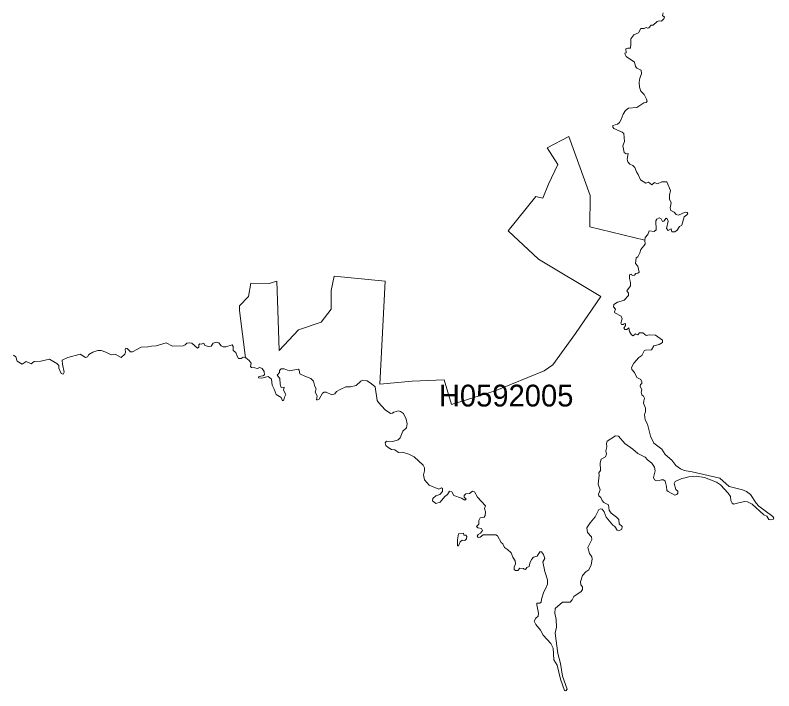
# Model space of a CAD drawing. Extents: x 369010 to 739155, y 6377141 to 6616555.
# Drawn here: x 428344 to 431823, y 6458107 to 6461206 of the extents above; entities that cross this region are included whole.
import ezdxf
from ezdxf.enums import TextEntityAlignment as Align

# ---------------------------------------------------------------- set-up
doc = ezdxf.new("R2010")
doc.units = 0
doc.header["$LTSCALE"] = 40
doc.layers.add('1', color=7, linetype='Continuous', lineweight=13)
doc.layers.add('2', color=7, linetype='Continuous')

msp = doc.modelspace()

# ---------------------------------------------------------------- linework, layer by layer
at = {"layer": '1'}
for points in [[(431238.22, 6460805.91), (431242.03, 6460812.03), (431240.04, 6460821.46), (431228.29, 6460842.48), (431213.73, 6460858.04), (431207.27, 6460875.91), (431206.28, 6460899.09), (431208.1, 6460918.28), (431216.54, 6460937.15), (431215.21, 6460953.54), (431195.52, 6460963.96), (431189.4, 6460971.41), (431185.09, 6460990.77), (431145.54, 6461017.09), (431140.9, 6461026.03), (431140.41, 6461032.15), (431146.03, 6461034.47), (431145.04, 6461051.35), (431153.98, 6461055.16), (431165.73, 6461055.16), (431168.21, 6461075.35), (431167.22, 6461097.52), (431180.79, 6461116.39), (431202.47, 6461124.83), (431213.23, 6461145.02), (431227.96, 6461145.52), (431237.72, 6461149.66), (431244.18, 6461146.85), (431249.97, 6461147.84), (431260.07, 6461160.58), (431270.49, 6461160.09), (431287.87, 6461177.96), (431297.3, 6461179.78), (431307.57, 6461178.95), (431318.49, 6461189.71), (431321.3, 6461197.65), (431312.37, 6461204.27), (431315.18, 6461216.52)], [(429544.62, 6459986.17), (429548.92, 6459852.77), (429554.71, 6459668.23), (429644.09, 6459763.4), (429747.86, 6459797.99), (429794.03, 6459858.56), (429793.7, 6459943.13), (429806.94, 6460009.17), (430041.3, 6459986.17), (430016.14, 6459514.64), (430165.42, 6459528.38), (430311.23, 6459533.02), (430345.66, 6459420.8), (430545.75, 6459483.86), (430769.84, 6459574.56), (430809.23, 6459602.2), (430914.16, 6459746.68), (431030.51, 6459915.83), (430743.69, 6460087.95), (430604.34, 6460217.04), (430732.11, 6460375.43), (430763.39, 6460367.82), (430789.54, 6460430.87), (430832.24, 6460521.57), (430784.57, 6460598.36), (430882.88, 6460649.84), (430981.52, 6460378.74), (430979.54, 6460236.08), (431231.27, 6460174.84), (431231.1, 6460175.01), (431233.59, 6460186.92), (431246.16, 6460200), (431251.46, 6460216.88), (431275.29, 6460214.56), (431284.23, 6460221.68), (431282.91, 6460263.05), (431287.54, 6460271.49), (431297.97, 6460276.13), (431305.91, 6460272.98), (431313.03, 6460260.74), (431319.15, 6460262.06), (431329.41, 6460275.8), (431334.21, 6460272.98), (431338.35, 6460262.06), (431331.4, 6460227.8), (431339.34, 6460218.86), (431352.09, 6460225.82), (431356.22, 6460212.74), (431369.96, 6460212.74), (431380.72, 6460220.19), (431391.48, 6460237.24), (431400.91, 6460243.36), (431411.83, 6460281.92), (431424.91, 6460289.87), (431429.21, 6460297.31), (431425.9, 6460301.62), (431415.97, 6460302.61), (431386.84, 6460289.37), (431376.08, 6460291.69), (431365.66, 6460302.11), (431350.6, 6460310.55), (431348.28, 6460322.8), (431352.58, 6460345.31), (431345.47, 6460361.86), (431345.47, 6460381.06), (431349.77, 6460402.24), (431332.23, 6460442.29), (431310.21, 6460442.29), (431289.53, 6460433.36), (431276.29, 6460438.49), (431264.04, 6460428.23), (431248.98, 6460439.98), (431236.4, 6460436.17), (431211.41, 6460450.74), (431201.15, 6460476.06), (431193.04, 6460487.81), (431186.42, 6460507.67), (431176.16, 6460517.1), (431162.92, 6460523.23), (431154.47, 6460534.48), (431150.67, 6460546.23), (431155.96, 6460571.22), (431146.03, 6460570.73), (431137.59, 6460576.35), (431130.97, 6460606.97), (431138.92, 6460626.67), (431135.77, 6460663.74), (431127.66, 6460670.36), (431090.09, 6460685.92), (431084.47, 6460692.54), (431085.29, 6460699.98), (431106.98, 6460706.6), (431115.91, 6460714.22), (431123.03, 6460727.29), (431132.96, 6460753.11), (431142.72, 6460768.67), (431156.46, 6460779.59), (431195.02, 6460783.73), (431226.47, 6460803.92), (431238.22, 6460805.91)], [(431184.1, 6460013.31), (431189.73, 6460021.75), (431199.16, 6460023.07), (431205.28, 6460027.38), (431200.15, 6460055.18), (431188.9, 6460067.76), (431191.71, 6460093.25), (431200.15, 6460097.38), (431208.1, 6460116.75), (431213.23, 6460132.31), (431233.59, 6460155.81), (431231.27, 6460174.84), (430979.54, 6460236.08), (430981.52, 6460378.74), (430882.88, 6460649.84), (430784.57, 6460598.36), (430832.24, 6460521.57), (430789.54, 6460430.87), (430763.39, 6460367.82), (430732.11, 6460375.43), (430604.34, 6460217.04), (430743.69, 6460087.95), (431030.51, 6459915.83), (430914.16, 6459746.68), (430809.23, 6459602.2), (430769.84, 6459574.56), (430545.75, 6459483.86), (430345.66, 6459420.8), (430311.23, 6459533.02), (430165.42, 6459528.38), (430016.14, 6459514.64), (430041.3, 6459986.17), (429806.94, 6460009.17), (429793.7, 6459943.13), (429794.03, 6459858.56), (429747.86, 6459797.99), (429644.09, 6459763.4), (429554.71, 6459668.23), (429548.92, 6459852.77), (429544.62, 6459986.17), (429508.87, 6459975.41), (429425.29, 6459977.06), (429413.87, 6459915.5), (429372.82, 6459873.95), (429372.82, 6459852.44), (429401.13, 6459635.3)], [(431631.95, 6458967.65), (431640.39, 6458962.85), (431655.46, 6458968.48), (431689.71, 6458976.09), (431702.96, 6458974.11), (431724.14, 6458963.35), (431778.09, 6458914.03), (431790.84, 6458907.91), (431800.77, 6458893.18), (431809.71, 6458891.36), (431820.96, 6458893.18), (431823.28, 6458898.97), (431819.14, 6458907.41), (431754.26, 6458954.91), (431742.01, 6458967.98), (431716.53, 6459007.04), (431698.65, 6459021.28), (431680.28, 6459028.72), (431617.72, 6459044.28), (431576.34, 6459082.84), (431448.41, 6459112.47), (431412.66, 6459117.6), (431394.79, 6459126.04), (431374.6, 6459140.27), (431355.73, 6459165.1), (431324.28, 6459191.91), (431309.22, 6459215.91), (431272.48, 6459243.71), (431257.91, 6459274.83), (431243.35, 6459330.27), (431233.59, 6459349.97), (431230.77, 6459374.96), (431235.41, 6459386.71), (431235.41, 6459403.59), (431224.98, 6459426.76), (431226.97, 6459437.52), (431230.77, 6459449.77), (431225.97, 6459458.21), (431218.53, 6459465.32), (431215.21, 6459477.08), (431217.53, 6459488.33), (431210.08, 6459504.22), (431212.4, 6459512.33), (431218.53, 6459516.47), (431218.03, 6459525.07), (431212.9, 6459535.83), (431195.35, 6459543.77), (431184.1, 6459566.78), (431172.85, 6459581.01), (431171.03, 6459590.78), (431181.78, 6459610.64), (431203.96, 6459636.95), (431217.53, 6459644.9), (431228.29, 6459666.58), (431234.91, 6459670.38), (431261.72, 6459670.88), (431272.98, 6459689.58), (431296.97, 6459695.71), (431312.03, 6459705.14), (431312.03, 6459715.07), (431280.09, 6459739.07), (431253.78, 6459739.56), (431237.72, 6459736.75), (431222.66, 6459748.83), (431207.6, 6459749.33), (431200.15, 6459739.9), (431188.9, 6459744.2), (431178.97, 6459736.25), (431170.03, 6459740.39), (431161.59, 6459755.45), (431158.78, 6459772), (431149.84, 6459763.89), (431140.41, 6459764.39), (431136.1, 6459771.01), (431142.72, 6459783.26), (431142.72, 6459791.7), (431137.1, 6459790.71), (431132.46, 6459787.06), (431124.35, 6459787.4), (431121.54, 6459793.19), (431127.66, 6459814.21), (431123.86, 6459825.13), (431094.73, 6459840.69), (431092.91, 6459845.32), (431096.71, 6459858.07), (431088.6, 6459869.32), (431089.6, 6459879.75), (431106.48, 6459890.01), (431123.03, 6459894.31), (431137.1, 6459898.45), (431157.29, 6459920.63), (431156.79, 6459931.88), (431148.85, 6459941.81), (431166.23, 6459965.31), (431165.73, 6459979.88), (431161.59, 6459998.74), (431161.59, 6460015.63), (431170.53, 6460018.94), (431174.17, 6460012.81), (431184.1, 6460013.31)], [(428337.27, 6459647.21), (428347.53, 6459638.77), (428353.65, 6459619.57), (428376.32, 6459605.84), (428394.53, 6459617.59), (428417.7, 6459606.83), (428431.77, 6459618.08), (428462.39, 6459619.57), (428502.27, 6459628.51), (428535.71, 6459609.15), (428544.15, 6459599.22), (428544.15, 6459587.96), (428555.9, 6459562.14), (428564.83, 6459560.16), (428569.63, 6459568.27), (428561.03, 6459605.01), (428560.2, 6459623.71), (428586.02, 6459636.95), (428641.96, 6459651.52), (428666.95, 6459635.46), (428676.38, 6459639.27), (428682.01, 6459649.7), (428700.38, 6459660.95), (428722.89, 6459667.9), (428737.95, 6459667.57), (428760.13, 6459660.95), (428784.13, 6459648.21), (428802.33, 6459651.52), (428830.14, 6459635.46), (428847.02, 6459651.02), (428850.82, 6459660.95), (428848.01, 6459673.53), (428851.32, 6459678.82), (428858.44, 6459677.83), (428873, 6459661.45), (428881.94, 6459661.45), (428922.32, 6459683.96), (428951.95, 6459685.44), (428968.83, 6459688.59), (428991.01, 6459689.09), (429037.18, 6459703.32), (429066.31, 6459688.26), (429114.14, 6459689.09), (429124.57, 6459693.89), (429131.69, 6459701.83), (429141.45, 6459704.15), (429154.19, 6459701.33), (429180.01, 6459679.32), (429187.13, 6459682.96), (429187.13, 6459694.38), (429191.43, 6459699.51), (429197.89, 6459697.2), (429209.64, 6459701.33), (429213.94, 6459691.4), (429230.33, 6459686.27), (429243.07, 6459688.59), (429252.01, 6459701.83), (429265.25, 6459706.13), (429277.49, 6459702.82), (429288.75, 6459689.58), (429298.68, 6459685.78), (429309.93, 6459684.45), (429339.56, 6459694.71), (429343.7, 6459686.27), (429344.19, 6459668.89), (429356.94, 6459659.46), (429361.57, 6459643.08), (429368.19, 6459631.32), (429380.93, 6459631.82), (429389.37, 6459637.45), (429401.13, 6459635.3), (429372.82, 6459852.44), (429372.82, 6459873.95), (429413.87, 6459915.5), (429425.29, 6459977.06), (429508.87, 6459975.41), (429544.62, 6459986.17)], [(429401.13, 6459635.3), (429402.12, 6459634.97), (429418.01, 6459622.88), (429426.94, 6459610.64), (429422.81, 6459594.58), (429427.94, 6459590.28), (429443, 6459589.45), (429453.26, 6459586.14), (429466, 6459590.28), (429477.26, 6459585.65), (429485.37, 6459572.41), (429487.19, 6459556.52), (429480.57, 6459552.71), (429462.36, 6459548.41), (429459.38, 6459542.78), (429475.44, 6459540.96), (429504.57, 6459548.9), (429519.63, 6459536.66), (429522.94, 6459509.84), (429532.37, 6459491.14), (429541.8, 6459467.14), (429564.81, 6459453.41), (429569.94, 6459437.02), (429576.56, 6459442.15), (429578.88, 6459454.9), (429585.99, 6459466.15), (429575.24, 6459486.01), (429577.55, 6459500.08), (429564.31, 6459498.59), (429559.18, 6459514.64), (429558.19, 6459539.97), (429546.44, 6459555.52), (429556.86, 6459567.77), (429556.86, 6459577.21), (429564.81, 6459583.83), (429578.05, 6459584.32), (429601.05, 6459575.72), (429643.42, 6459582.34), (429647.06, 6459577.7), (429649.88, 6459561.65), (429672.55, 6459550.89), (429699.36, 6459540.46), (429712.94, 6459528.22), (429718.07, 6459502.89), (429723.86, 6459491.97), (429720.55, 6459476.58), (429728.49, 6459461.02), (429726.67, 6459442.15), (429730.81, 6459441.66), (429737.93, 6459445.46), (429753.81, 6459472.77), (429761.92, 6459477.41), (429770.86, 6459477.41), (429796.68, 6459465.16), (429809.42, 6459468.97), (429818.36, 6459480.22), (429833.92, 6459489.16), (429860.23, 6459500.91), (429881.42, 6459500.91), (429908.23, 6459507.53), (429929.25, 6459528.22), (429938.68, 6459531.53), (429958.87, 6459528.71), (429978.73, 6459515.64), (429994.62, 6459501.9), (430003.56, 6459439.34), (430009.68, 6459429.08), (430040.8, 6459396.47), (430066.12, 6459380.09), (430074.23, 6459381.08), (430080.85, 6459385.72), (430101.54, 6459391.84), (430111.8, 6459389.03), (430124.54, 6459378.6), (430136.79, 6459353.28), (430142.42, 6459332.09), (430138.11, 6459313.72), (430122.23, 6459297.83), (430109.98, 6459267.71), (430100.55, 6459258.28), (430076.55, 6459250.67), (430047.42, 6459251.66), (430040.8, 6459244.21), (430044.11, 6459231.96), (430054.04, 6459223.52), (430069.43, 6459214.92), (430085.98, 6459212.6), (430101.87, 6459200.85), (430120.74, 6459202.34), (430149.87, 6459192.9), (430173.37, 6459180.66), (430215.9, 6459142.59), (430221.69, 6459129.35), (430221.69, 6459115.78), (430216.89, 6459098.4), (430221.2, 6459074.73), (430243.21, 6459050.41), (430286.57, 6459032.03), (430298.82, 6459038.66), (430304.61, 6459034.85)], [(430827.11, 6458399.31), (430824.79, 6458435.06), (430819.16, 6458463.69), (430820.16, 6458485.38), (430854.42, 6458513.68), (430889.34, 6458513.68), (430899.1, 6458524.43), (430906.22, 6458540.49), (430940.48, 6458562.5), (430946.11, 6458571.44), (430945.61, 6458584.18), (430937.66, 6458594.11), (430936.34, 6458607.19), (430945.61, 6458636.81), (430960.67, 6458652.87), (430974.41, 6458662.8), (430985.66, 6458685.3), (430989.96, 6458710.79), (430989.47, 6458722.05), (430978.54, 6458737.6), (430970.6, 6458765.24), (430988.47, 6458801.98), (430987.15, 6458813.74), (430968.28, 6458833.93), (430965.47, 6458854.28), (430980.53, 6458877.79), (431003.54, 6458904.93), (431021.41, 6458938.86), (431028.53, 6458942.66), (431035.97, 6458939.85), (431045.9, 6458927.6), (431054.84, 6458904.1), (431084.96, 6458866.37), (431093.9, 6458860.74), (431104.66, 6458844.35), (431111.77, 6458841.54), (431125.84, 6458849.48), (431127.66, 6458861.23), (431114.59, 6458872.99), (431112.27, 6458893.67), (431101.84, 6458904.1), (431077.35, 6458921.97), (431067.92, 6458936.04), (431064.77, 6458960.54), (431044.41, 6458971.29), (431035.48, 6458980.23), (431029.85, 6458993.97), (431021.41, 6459000.92), (431019.09, 6459009.03), (431026.54, 6459029.22), (431018.1, 6459054.54), (431022.9, 6459096.91), (431020.91, 6459107.67), (431028.53, 6459117.6), (431027.04, 6459152.85), (431031.67, 6459170.23), (431051.53, 6459180.66), (431056.17, 6459192.41), (431052.52, 6459207.47), (431058.15, 6459226.83), (431055.67, 6459241.4), (431059.48, 6459251.66), (431096.71, 6459277.48), (431111.28, 6459275.66), (431140.41, 6459241.73), (431177.48, 6459215.41), (431199.16, 6459195.72), (431232.59, 6459179.66), (431244.34, 6459166.59), (431264.54, 6459151.53), (431276.29, 6459133.16), (431279.1, 6459117.1), (431271.16, 6459085.16), (431276.78, 6459074.4), (431285.22, 6459071.09), (431298.46, 6459072.42), (431305.91, 6459075.73), (431317.33, 6459074.4), (431324.78, 6459069.11), (431330.9, 6459044.78), (431332.23, 6459026.41), (431339.34, 6459020.78), (431369.46, 6459005.22), (431378.4, 6459007.04), (431383.53, 6459013.66), (431382.7, 6459023.1), (431374.1, 6459030.55), (431365.66, 6459057.85), (431370.46, 6459067.29), (431400.91, 6459081.85), (431415.97, 6459084.17), (431433.85, 6459089.46), (431466.78, 6459091.29), (431505.34, 6459085.16), (431560.46, 6459064.97), (431578.83, 6459051.73), (431613.58, 6459014.66), (431623.84, 6458998.6), (431625.83, 6458980.23), (431631.95, 6458967.65)], [(430304.61, 6459034.85), (430304.61, 6459021.61), (430291.87, 6459008.04), (430272.67, 6459001.91), (430259.43, 6458989.67), (430258.11, 6458979.24), (430273.17, 6458966.66), (430293.36, 6458972.78), (430314.05, 6458998.11), (430326.29, 6459007.54), (430336.22, 6459022.6), (430345.99, 6459020.28), (430356.41, 6459002.91), (430391.67, 6458990.66), (430406.73, 6458981.23), (430411.86, 6458985.86), (430402.92, 6458995.79), (430402.92, 6459003.73), (430410.53, 6459011.35), (430427.42, 6459012.67), (430440.99, 6459022.6), (430450.42, 6459019.29), (430464.16, 6458995.79), (430501.23, 6458956.23), (430496.93, 6458943.49), (430501.73, 6458928.1), (430500.24, 6458911.55), (430495.6, 6458904.1), (430476.74, 6458900.29), (430471.11, 6458888.54), (430471.11, 6458871.66), (430459.36, 6458860.24), (430465.98, 6458855.61), (430482.36, 6458851.3), (430487.66, 6458842.04), (430478.23, 6458830.62), (430467.3, 6458824.49), (430462.67, 6458816.55), (430467.3, 6458810.92), (430477.23, 6458812.41), (430490.47, 6458823.17), (430548.23, 6458822.18), (430556.34, 6458817.54), (430572.23, 6458787.42), (430579.85, 6458780.8), (430588.29, 6458763.92), (430601.86, 6458755.48), (430618.9, 6458740.42), (430626.85, 6458720.06), (430637.11, 6458704.17), (430638.6, 6458690.1), (430631.98, 6458674.05), (430632.97, 6458663.62), (430639.1, 6458658.49), (430648.86, 6458659.49), (430658.29, 6458670.24), (430675.34, 6458668.92), (430678.98, 6458664.62), (430684.61, 6458664.12), (430691.23, 6458673.06), (430701.66, 6458678.19), (430703.97, 6458692.42), (430712.41, 6458710.3), (430721.85, 6458719.73), (430738.23, 6458724.36), (430749.65, 6458744.06), (430757.6, 6458745.05), (430766.53, 6458733.3), (430773.15, 6458714.1), (430764.71, 6458699.37), (430773.65, 6458654.69), (430785.4, 6458615.79), (430784.9, 6458596.92), (430775.47, 6458571.44), (430768.85, 6458560.68), (430758.09, 6458527.74), (430756.11, 6458513.18), (430749.98, 6458509.87), (430736.91, 6458508.88), (430735.92, 6458502.42), (430743.86, 6458463.69), (430742.04, 6458450.12), (430731.78, 6458440.19), (430724.16, 6458427.12), (430732.11, 6458411.06), (430753.29, 6458384.75), (430765.04, 6458362.24), (430801.29, 6458324.01), (430811.22, 6458303.32), (430814.03, 6458249.7), (430830.42, 6458224.38), (430844.65, 6458160.82), (430862.86, 6458108.19), (430868.98, 6458107.2), (430875.1, 6458114.32), (430853.59, 6458174.56), (430844.65, 6458233.31), (430833.23, 6458278.99), (430820.98, 6458371.51), (430827.11, 6458399.31)]]:
    msp.add_lwpolyline(points, dxfattribs=at)
msp.add_lwpolyline([(430400.11, 6458831.11), (430377.6, 6458827.8), (430371.97, 6458799.67), (430371.97, 6458772.36), (430377.6, 6458772.36), (430385.05, 6458791.23), (430393.98, 6458797.68), (430406.73, 6458796.85), (430413.35, 6458804.8), (430415.67, 6458815.22), (430411.36, 6458820.85), (430402.42, 6458820.85)], close=True, dxfattribs=at)

# ---------------------------------------------------------------- texts
at = {"layer": '2'}
msp.add_text('H0592005', height=100, dxfattribs=at).set_placement((430595.67, 6459411.48), align=Align.CENTER)

doc.saveas('drawing.dxf')
